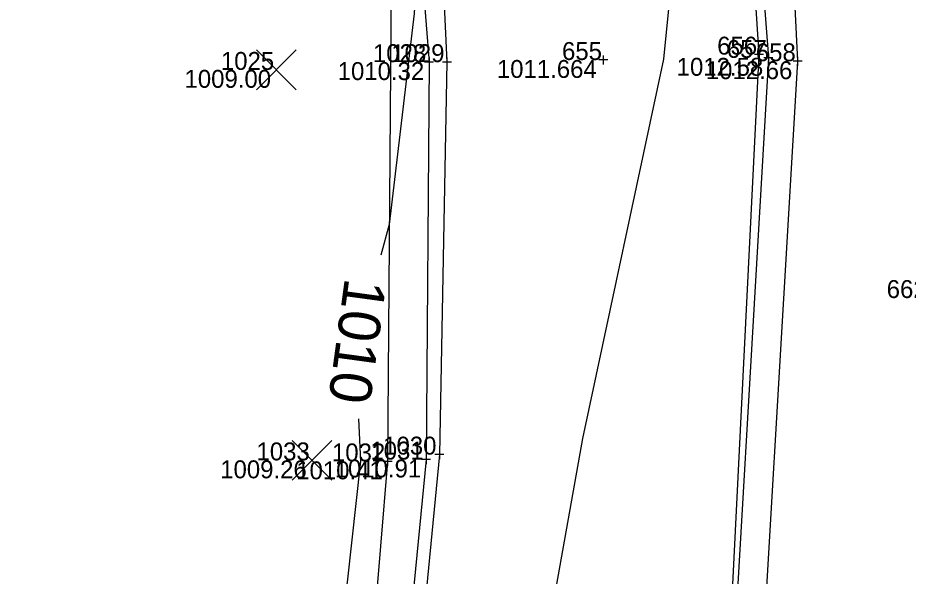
# Model space of a CAD drawing. Extents: x 2354693 to 2355622, y 637071 to 710080.
# Drawn here: x 2355324.2 to 2355383.9, y 709182.9 to 709220.3 of the extents above; entities that cross this region are included whole.
import ezdxf

# ---------------------------------------------------------------- set-up
doc = ezdxf.new("R2010")
doc.units = 0
for name, color, linetype in [('DT_X_Contour_Major', 7, 'Continuous'), ('DT_X_Contour_Minor', 7, 'Continuous'), ('PM_X_Surveyed_Line', 7, 'Continuous'), ('PV_X_EOP', 7, 'Continuous'), ('PV_X_Shoulder', 7, 'Continuous'), ('SV_X_Random_Point', 7, 'Continuous'), ('SV_X_Shot_Marker', 7, 'Continuous'), ('SV_X_Text_Elevation', 7, 'Continuous'), ('SV_X_Text_Name', 7, 'Continuous')]:
    doc.layers.add(name, color=color, linetype=linetype)

msp = doc.modelspace()

# ---------------------------------------------------------------- linework, layer by layer
at = {"layer": 'DT_X_Contour_Major'}
for points in [[(2355382.151, 709274.282), (2355381.711, 709274.976), (2355380.703, 709275.914), (2355376.833, 709277.662), (2355375.801, 709278.001), (2355375.775, 709278.159), (2355374.352, 709276.373), (2355372.639, 709275.689), (2355367.547, 709272.887), (2355358.064, 709270.769), (2355356.817, 709270.34), (2355349.492, 709267.71), (2355349.176, 709262.706), (2355350.806, 709240.105), (2355350.736, 709238.617), (2355350.394, 709234.495), (2355350.966, 709223.924), (2355350.775, 709220.637), (2355349.098, 709206.498), (2355348.523, 709204.444)], [(2355382.151, 709274.282), (2355381.711, 709274.976), (2355380.703, 709275.914), (2355376.833, 709277.662), (2355375.801, 709278.001), (2355375.775, 709278.159), (2355374.352, 709276.373), (2355372.639, 709275.689), (2355367.547, 709272.887), (2355358.064, 709270.769), (2355356.817, 709270.34), (2355349.492, 709267.71), (2355349.176, 709262.706), (2355350.806, 709240.105), (2355350.736, 709238.617), (2355350.394, 709234.495), (2355350.966, 709223.924), (2355350.775, 709220.637), (2355349.098, 709206.498), (2355348.523, 709204.444)], [(2355347.035, 709193.486), (2355347.171, 709190.656), (2355346.282, 709182.542), (2355344.272, 709168.584), (2355339.687, 709145.301), (2355339.229, 709144.664), (2355328.796, 709128.819), (2355329.274, 709120.278), (2355328.853, 709117.463), (2355322.247, 709098.569)], [(2355347.035, 709193.486), (2355347.171, 709190.656), (2355346.282, 709182.542), (2355344.272, 709168.584), (2355339.687, 709145.301), (2355339.229, 709144.664), (2355328.796, 709128.819), (2355329.274, 709120.278), (2355328.853, 709117.463), (2355322.247, 709098.569)]]:
    msp.add_lwpolyline(points, dxfattribs=at)
at = {"layer": 'DT_X_Contour_Minor'}
msp.add_lwpolyline([(2355388.382, 709181.549), (2355387.248, 709201.609), (2355389.188, 709218.85), (2355383.697, 709231.486), (2355379.499, 709244.29), (2355376.776, 709247.498), (2355376.105, 709247.453), (2355373.371, 709254.729), (2355371.839, 709253.134), (2355371.28, 709251.764), (2355370.025, 709243.384), (2355369.092, 709233.774), (2355367.481, 709217.574), (2355362.053, 709192.157), (2355358.45, 709172.035)], dxfattribs=at)
msp.add_lwpolyline([(2355388.382, 709181.549), (2355387.248, 709201.609), (2355389.188, 709218.85), (2355383.697, 709231.486), (2355379.499, 709244.29), (2355376.776, 709247.498), (2355376.105, 709247.453), (2355373.371, 709254.729), (2355371.839, 709253.134), (2355371.28, 709251.764), (2355370.025, 709243.384), (2355369.092, 709233.774), (2355367.481, 709217.574), (2355362.053, 709192.157), (2355358.45, 709172.035)], dxfattribs=at)
at = {"layer": 'PM_X_Surveyed_Line'}
for points in [[(2355180.148, 709561.237), (2355214.753, 709522.888), (2355249.307, 709484.271), (2355284.017, 709443.142), (2355315.552, 709399.77), (2355328.888, 709377.573), (2355342.967, 709349.789), (2355353.365, 709324.191), (2355361.351, 709299.648), (2355367.764, 709272.473), (2355372.191, 709243.487), (2355373.87, 709217.884), (2355371.213, 709164.414), (2355367.135, 709139.625), (2355360.061, 709111.877), (2355351.618, 709085.78), (2355342.505, 709062.338), (2355329.445, 709031.419), (2355320.624, 709012.583)], [(2355165.86, 709547.265), (2355199.549, 709510.037), (2355233.994, 709470.593), (2355267.54, 709430.367), (2355282.605, 709410.565), (2355297.684, 709388.575), (2355309.404, 709369.446), (2355323.831, 709342.426), (2355334.056, 709318.38), (2355342.286, 709293.43), (2355348.466, 709267.168), (2355351.872, 709240.375), (2355352.964, 709217.38), (2355352.456, 709191.088), (2355350.186, 709167.624), (2355345.964, 709144.005), (2355339.847, 709117.861), (2355332.105, 709093.739), (2355322.597, 709069.077), (2355314.612, 709050.664), (2355300.362, 709021.696)]]:
    msp.add_lwpolyline(points, dxfattribs=at)
at = {"layer": 'PV_X_EOP'}
for points in [[(2355180.814, 709561.741), (2355215.64, 709523.556), (2355249.922, 709484.356), (2355284.407, 709443.36), (2355315.939, 709399.966), (2355329.751, 709378.355), (2355343.524, 709350.098), (2355349.219, 709351.4), (2355359.304, 709326.795), (2355367.588, 709301.754), (2355374.108, 709275.907), (2355368.17, 709272.694), (2355372.498, 709243.563), (2355374.502, 709217.665), (2355371.414, 709164.432), (2355367.842, 709139.325), (2355361.02, 709111.642), (2355352.388, 709085.56), (2355343.445, 709061.967), (2355330.49, 709031.083), (2355321.141, 709011.801)], [(2355165.324, 709546.951), (2355198.995, 709509.502), (2355233.405, 709470.111), (2355266.728, 709429.76), (2355281.934, 709410.085), (2355297.047, 709388.167), (2355308.637, 709369.042), (2355321.448, 709342.933), (2355321.339, 709342.62), (2355331.824, 709317.677), (2355340.036, 709292.971), (2355346.601, 709266.722), (2355349.963, 709239.902), (2355351.76, 709217.379), (2355351.561, 709190.756), (2355349.316, 709167.656), (2355345.615, 709144.125), (2355339.519, 709118.013), (2355331.95, 709093.674), (2355322.309, 709069.242), (2355314.268, 709051.111), (2355300.286, 709022.246)]]:
    msp.add_lwpolyline(points, dxfattribs=at)
at = {"layer": 'PV_X_Shoulder'}
for points in [[(2355370.563, 709271.651), (2355375.125, 709244.152), (2355376.457, 709217.439), (2355373.313, 709164.025), (2355369.833, 709138.826), (2355363.46, 709110.733), (2355354.734, 709084.843), (2355345.666, 709061.243), (2355332.683, 709029.848), (2355323.397, 709011.312)], [(2355350.692, 709226.183), (2355349.237, 709225.724), (2355348.983, 709190.632), (2355347.11, 709167.944), (2355343.481, 709144.038), (2355337.288, 709118.882), (2355329.716, 709094.535), (2355320.778, 709071.235), (2355312.538, 709052.234), (2355298.997, 709024.071)]]:
    msp.add_lwpolyline(points, dxfattribs=at)
at = {"layer": 'SV_X_Random_Point'}
for p, q in [((2355340.202, 709215.525), (2355342.869, 709218.195)), ((2355340.202, 709218.195), (2355342.869, 709215.525)), ((2355342.584, 709189.365), (2355345.251, 709192.035)), ((2355342.584, 709192.035), (2355345.251, 709189.365))]:
    msp.add_line(p, q, dxfattribs=at)
at = {"layer": 'SV_X_Shot_Marker'}
for p, q in [((2355363.436, 709217.822), (2355363.436, 709217.222)), ((2355374.17, 709217.884), (2355373.57, 709217.884)), ((2355373.87, 709218.184), (2355373.87, 709217.584)), ((2355374.502, 709217.965), (2355374.502, 709217.365)), ((2355352.059, 709217.379), (2355351.46, 709217.379)), ((2355351.76, 709217.679), (2355351.76, 709217.079)), ((2355353.264, 709217.38), (2355352.664, 709217.38)), ((2355352.964, 709217.68), (2355352.964, 709217.08)), ((2355363.736, 709217.522), (2355363.136, 709217.522)), ((2355374.802, 709217.665), (2355374.202, 709217.665)), ((2355376.757, 709217.439), (2355376.157, 709217.439)), ((2355376.457, 709217.739), (2355376.457, 709217.139)), ((2355351.561, 709191.056), (2355351.561, 709190.456)), ((2355352.756, 709191.088), (2355352.156, 709191.088)), ((2355352.456, 709191.388), (2355352.456, 709190.788)), ((2355349.283, 709190.632), (2355348.683, 709190.632)), ((2355348.983, 709190.932), (2355348.983, 709190.332)), ((2355351.86, 709190.756), (2355351.261, 709190.756))]:
    msp.add_line(p, q, dxfattribs=at)

# ---------------------------------------------------------------- texts
at = {"layer": 'DT_X_Contour_Major'}
msp.add_text('1010', height=2.8, rotation=262.27128, dxfattribs=at).set_placement((2355346.132, 709202.985))
msp.add_text('1010', height=2.8, rotation=262.27128, dxfattribs=at).set_placement((2355346.132, 709202.985))
at = {"layer": 'SV_X_Text_Elevation'}
for s, p in [('1010.32', (2355345.64, 709216.179)), ('1011.664', (2355356.308, 709216.322)), ('1012.58', (2355368.356, 709216.465)), ('1012.66', (2355370.307, 709216.239)), ('1009.00', (2355335.377, 709215.66)), ('1009.26', (2355337.768, 709189.5)), ('1010.41', (2355342.862, 709189.432)), ('1010.91', (2355345.439, 709189.556))]:
    msp.add_text(s, height=1.2, dxfattribs=at).set_placement(p)
at = {"layer": 'SV_X_Text_Name'}
for s, p in [('656', (2355371.071, 709217.884)), ('1028', (2355348.006, 709217.379)), ('1029', (2355349.228, 709217.38)), ('655', (2355360.673, 709217.522)), ('657', (2355371.716, 709217.665)), ('658', (2355373.662, 709217.439)), ('1025', (2355337.815, 709216.86)), ('662', (2355382.43, 709201.576)), ('1030', (2355348.69, 709191.088)), ('1033', (2355340.201, 709190.7)), ('1032', (2355345.257, 709190.632)), ('1031', (2355347.832, 709190.756))]:
    msp.add_text(s, height=1.2, dxfattribs=at).set_placement(p)

doc.saveas('drawing.dxf')
